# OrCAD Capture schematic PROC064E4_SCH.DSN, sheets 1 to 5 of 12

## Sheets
1 01. TABLE OF CONTENTS: title: TABLE OF CONTENTS; rev: E4; note: MS_TI_MAXIE_IDK_APPLICATION_CARD_SCH_REV E4
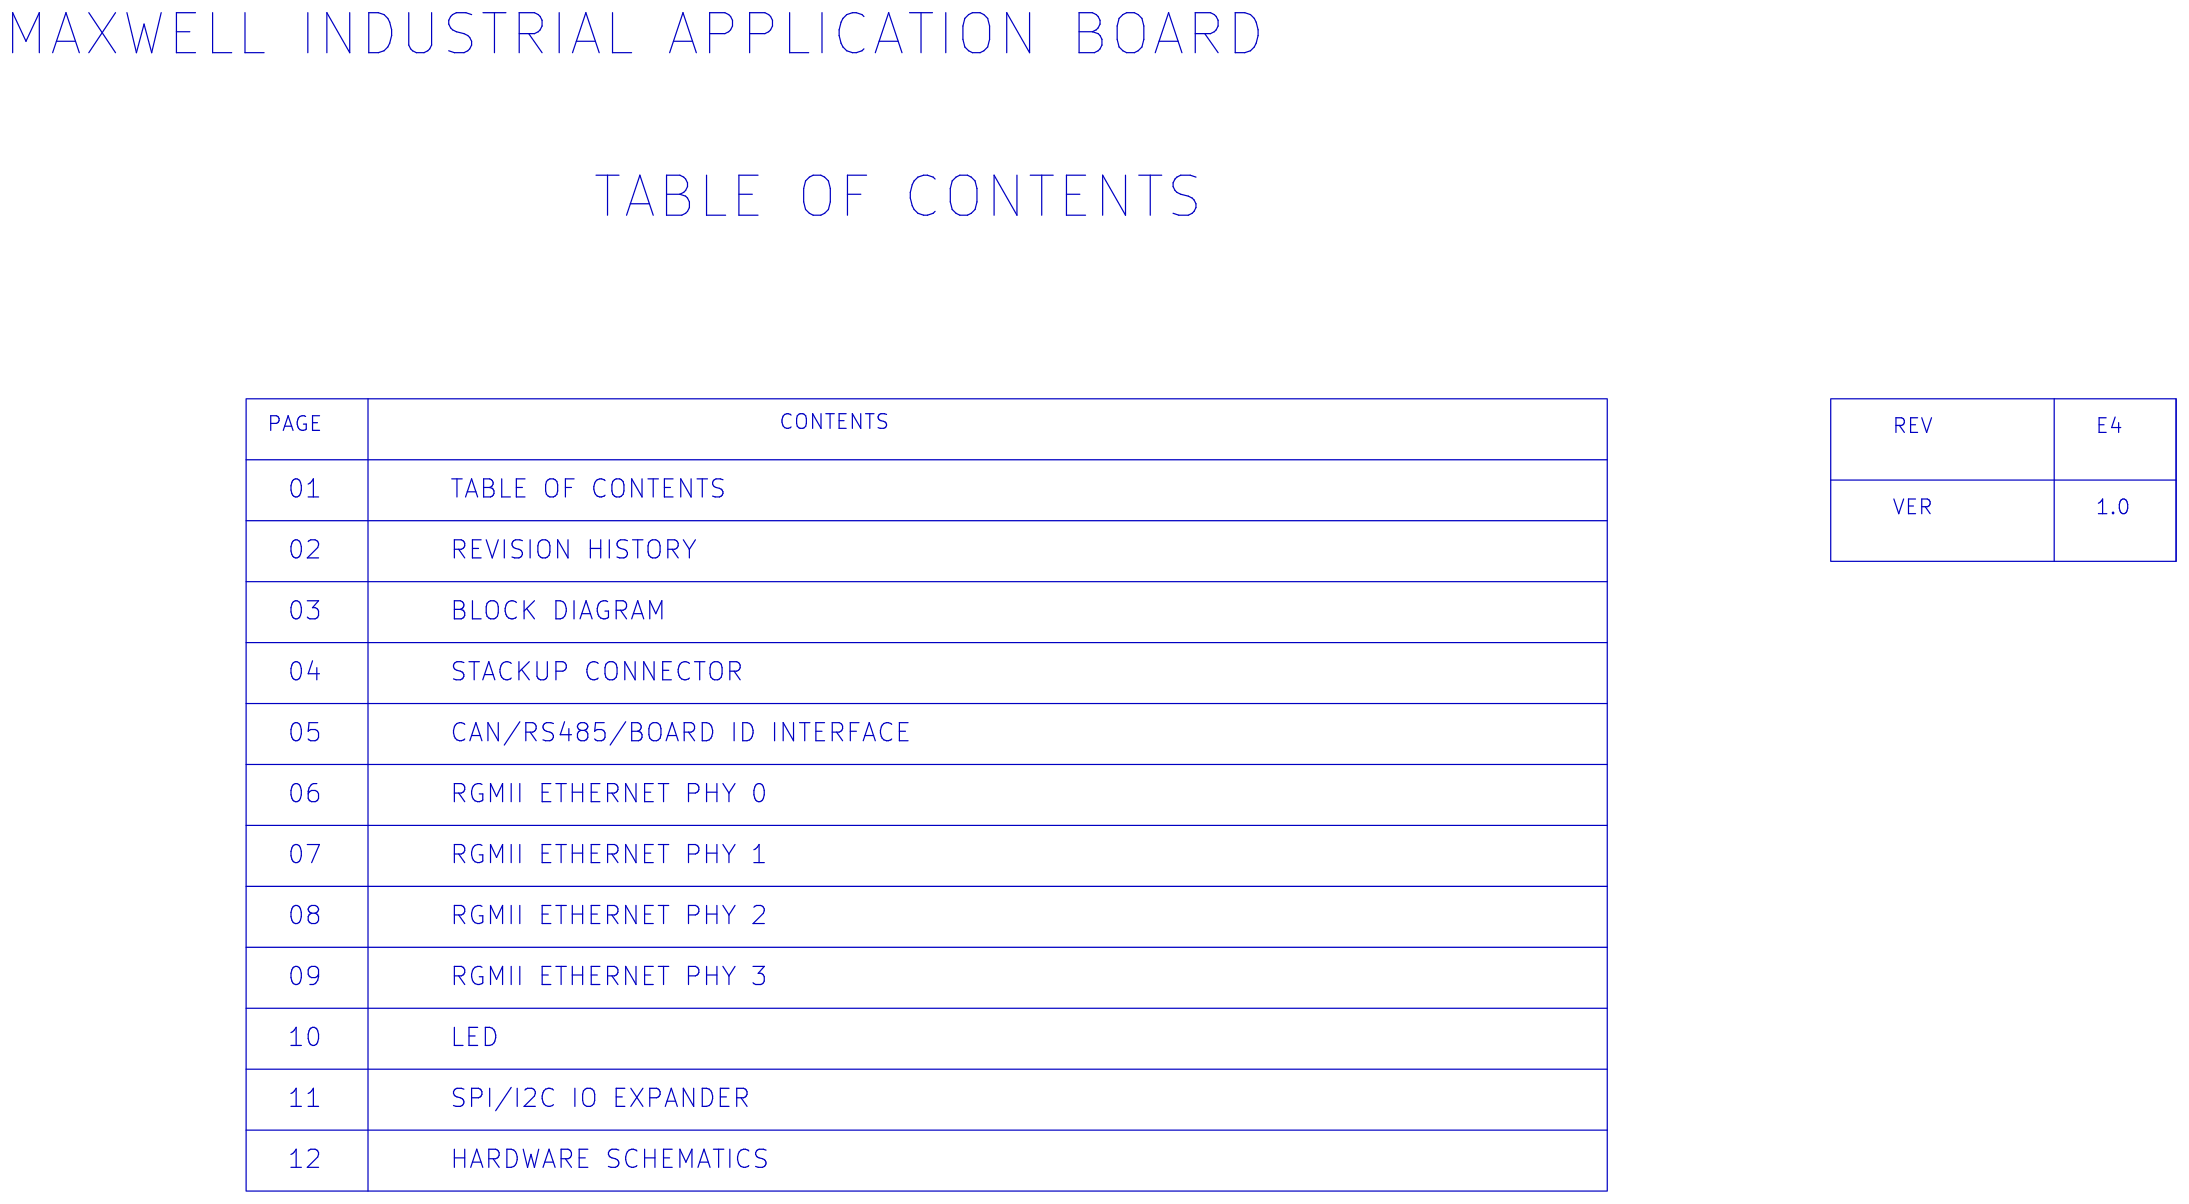
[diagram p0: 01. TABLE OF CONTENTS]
2 02. REVISION HISTORY: title: REVISION HISTORY
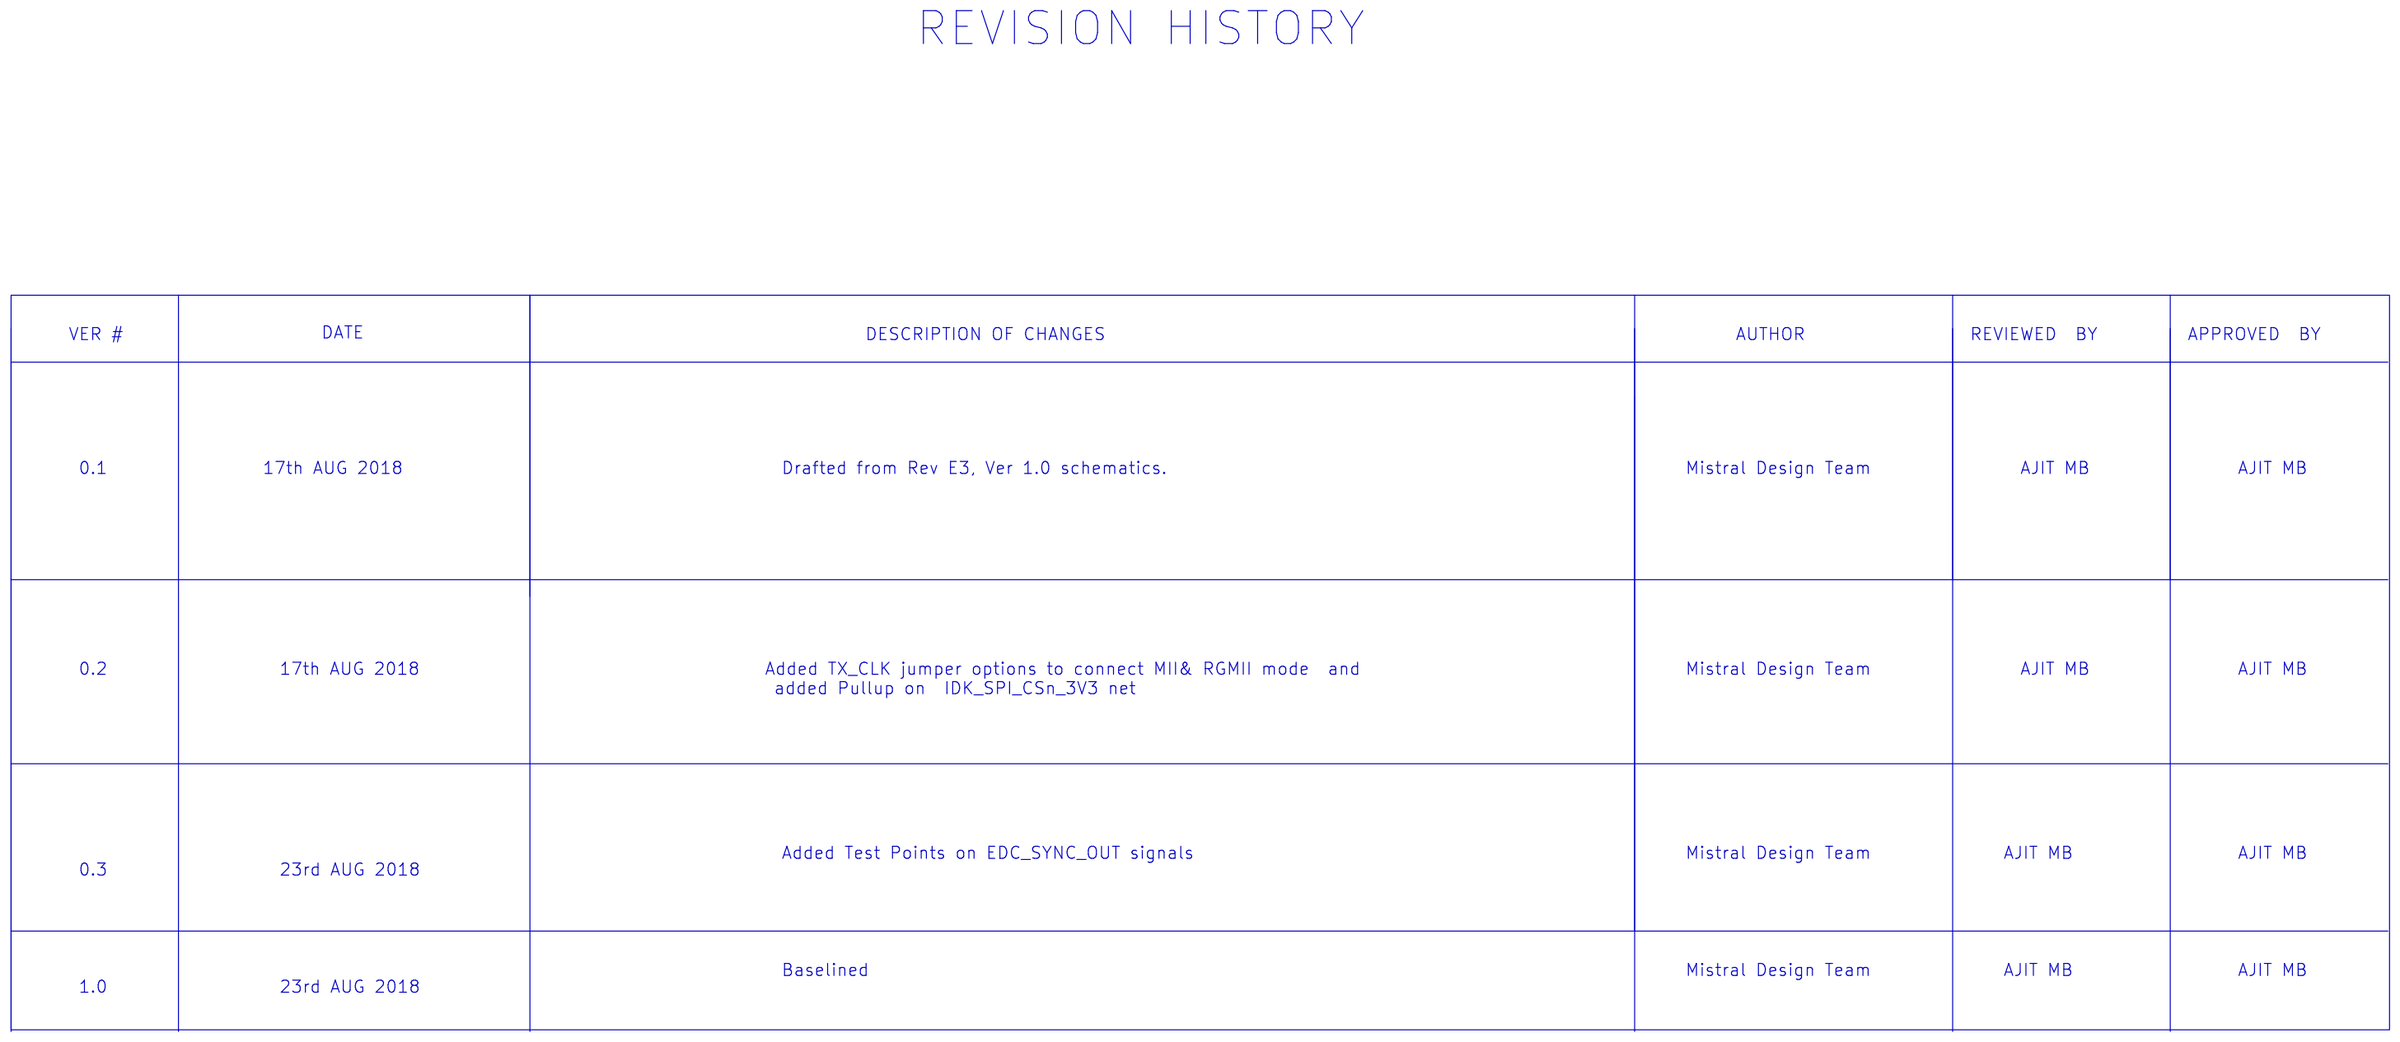
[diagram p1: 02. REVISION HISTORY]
3 03. BLOCK DIAGRAM: title: BLOCK DIAGRAM
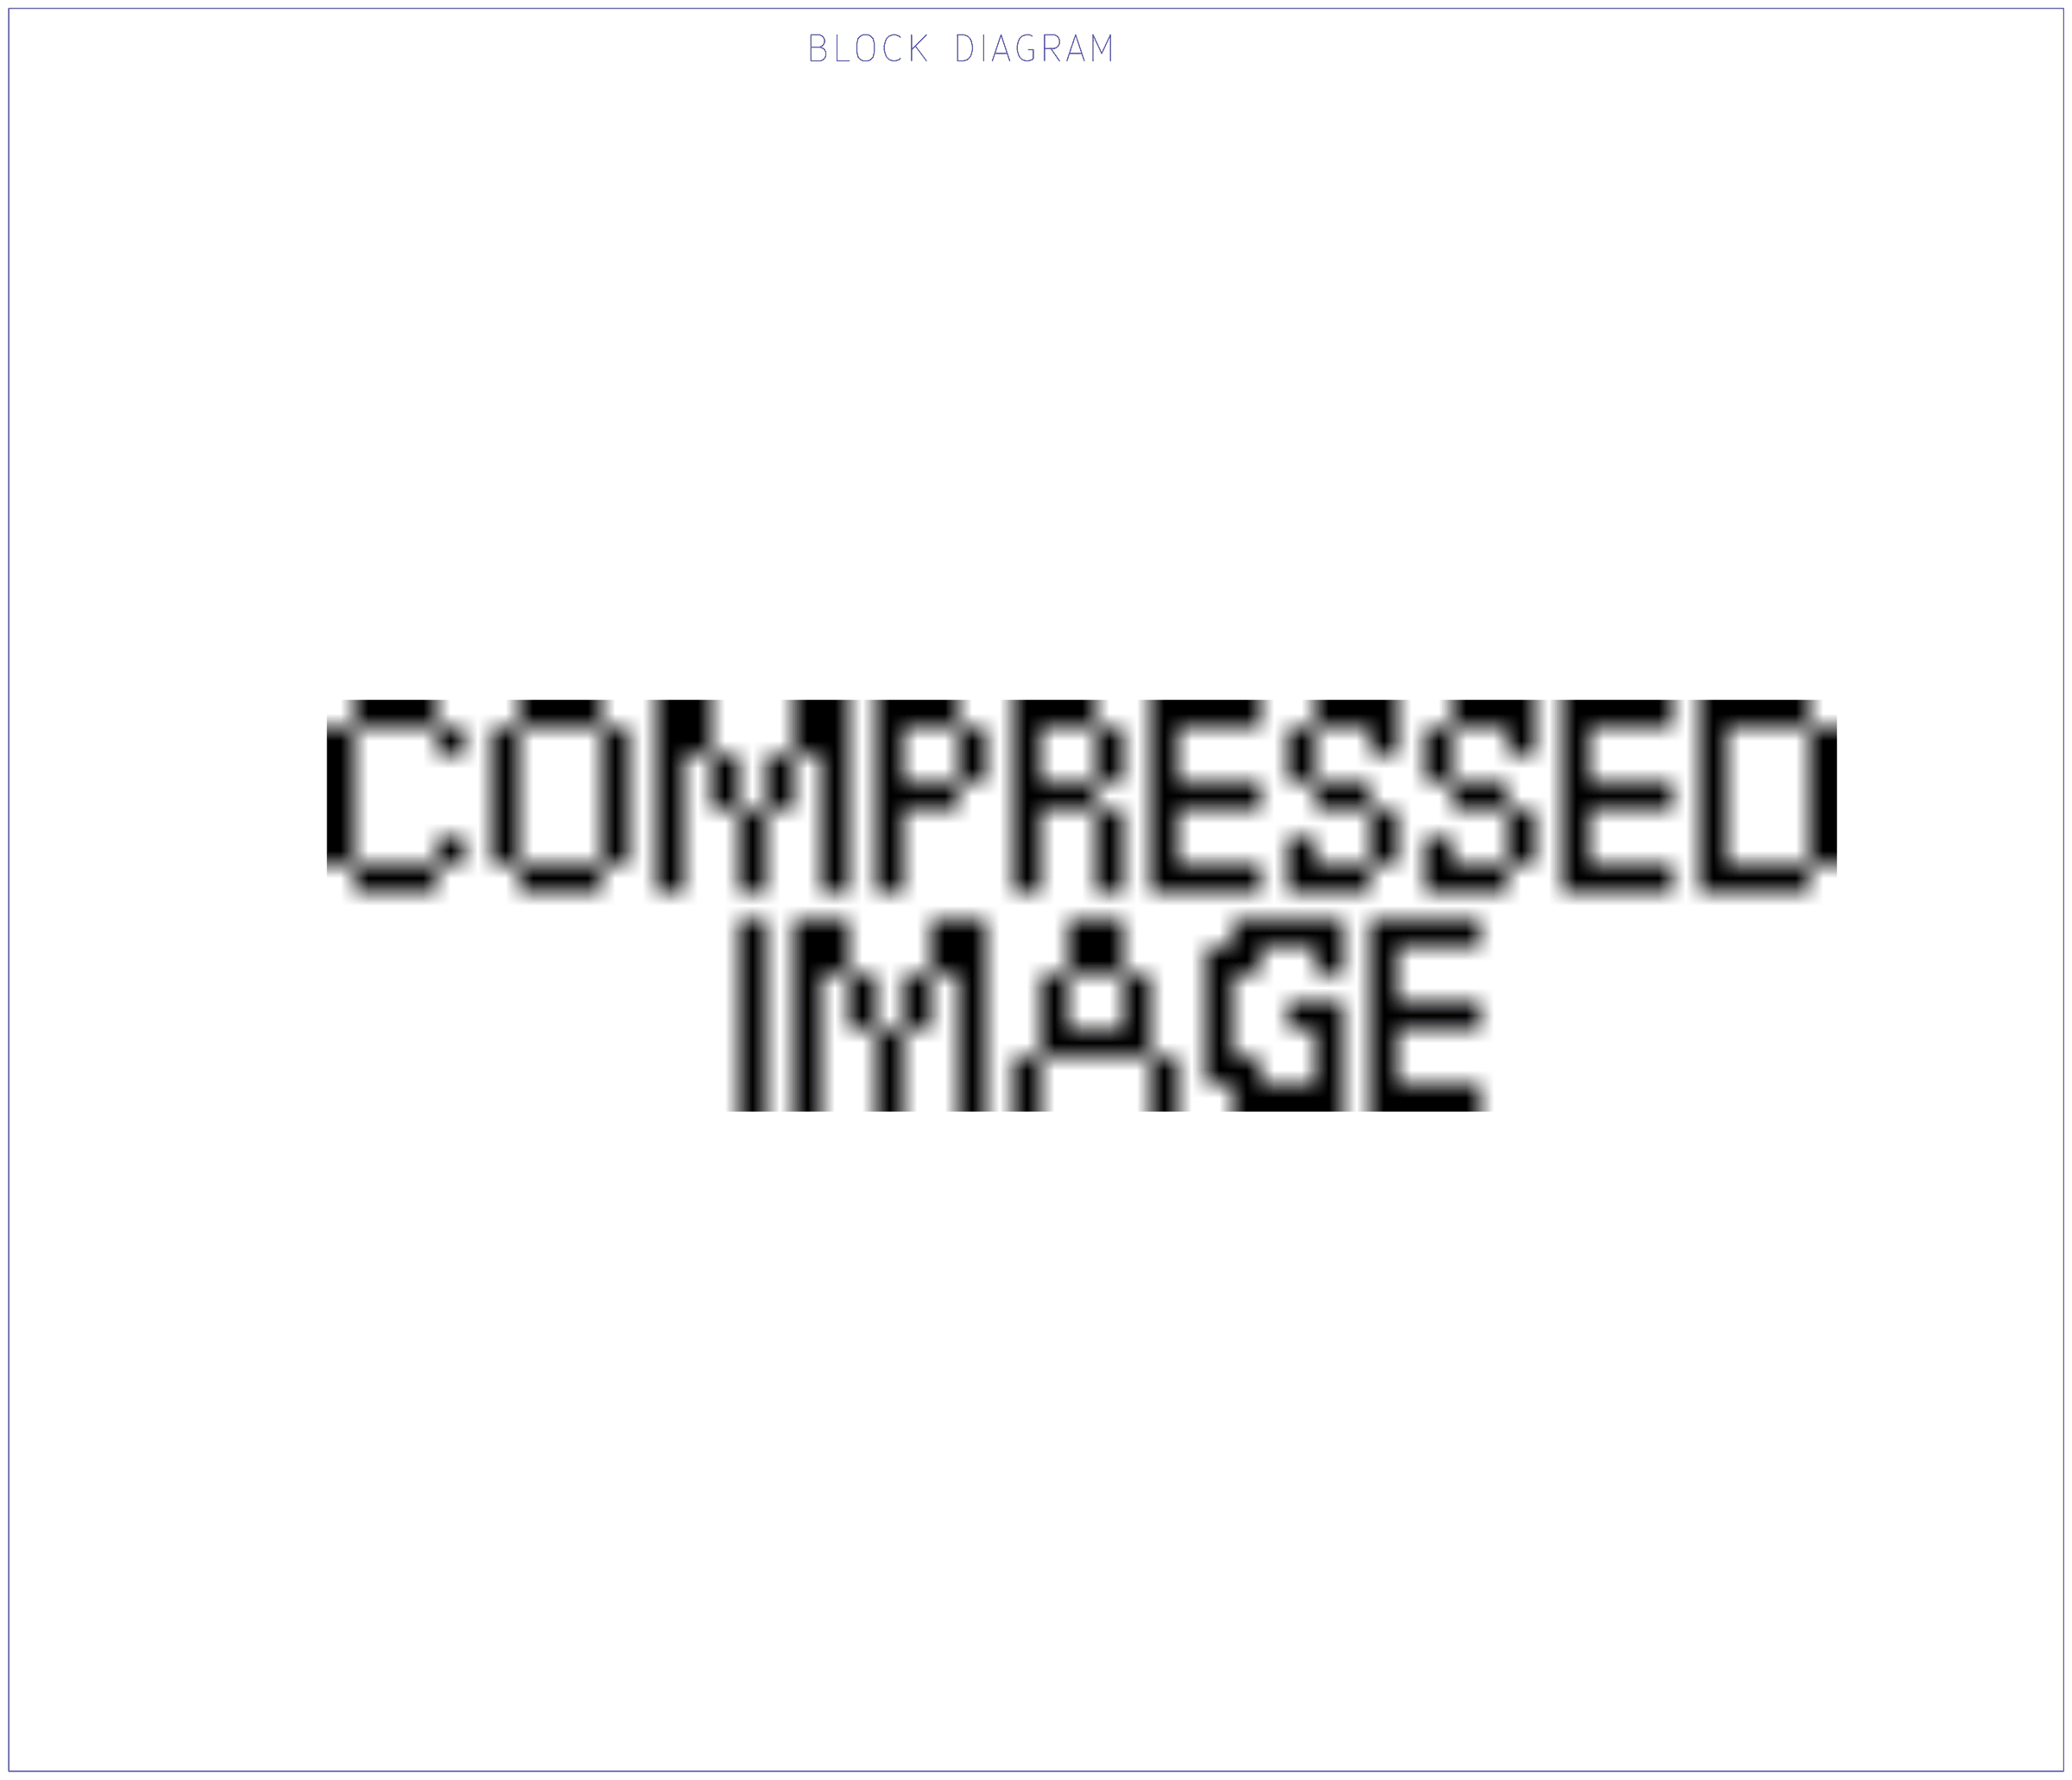
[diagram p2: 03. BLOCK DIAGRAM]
4 04. STACKUP CONNECTOR: size C; title: STACKUP CONNECTOR
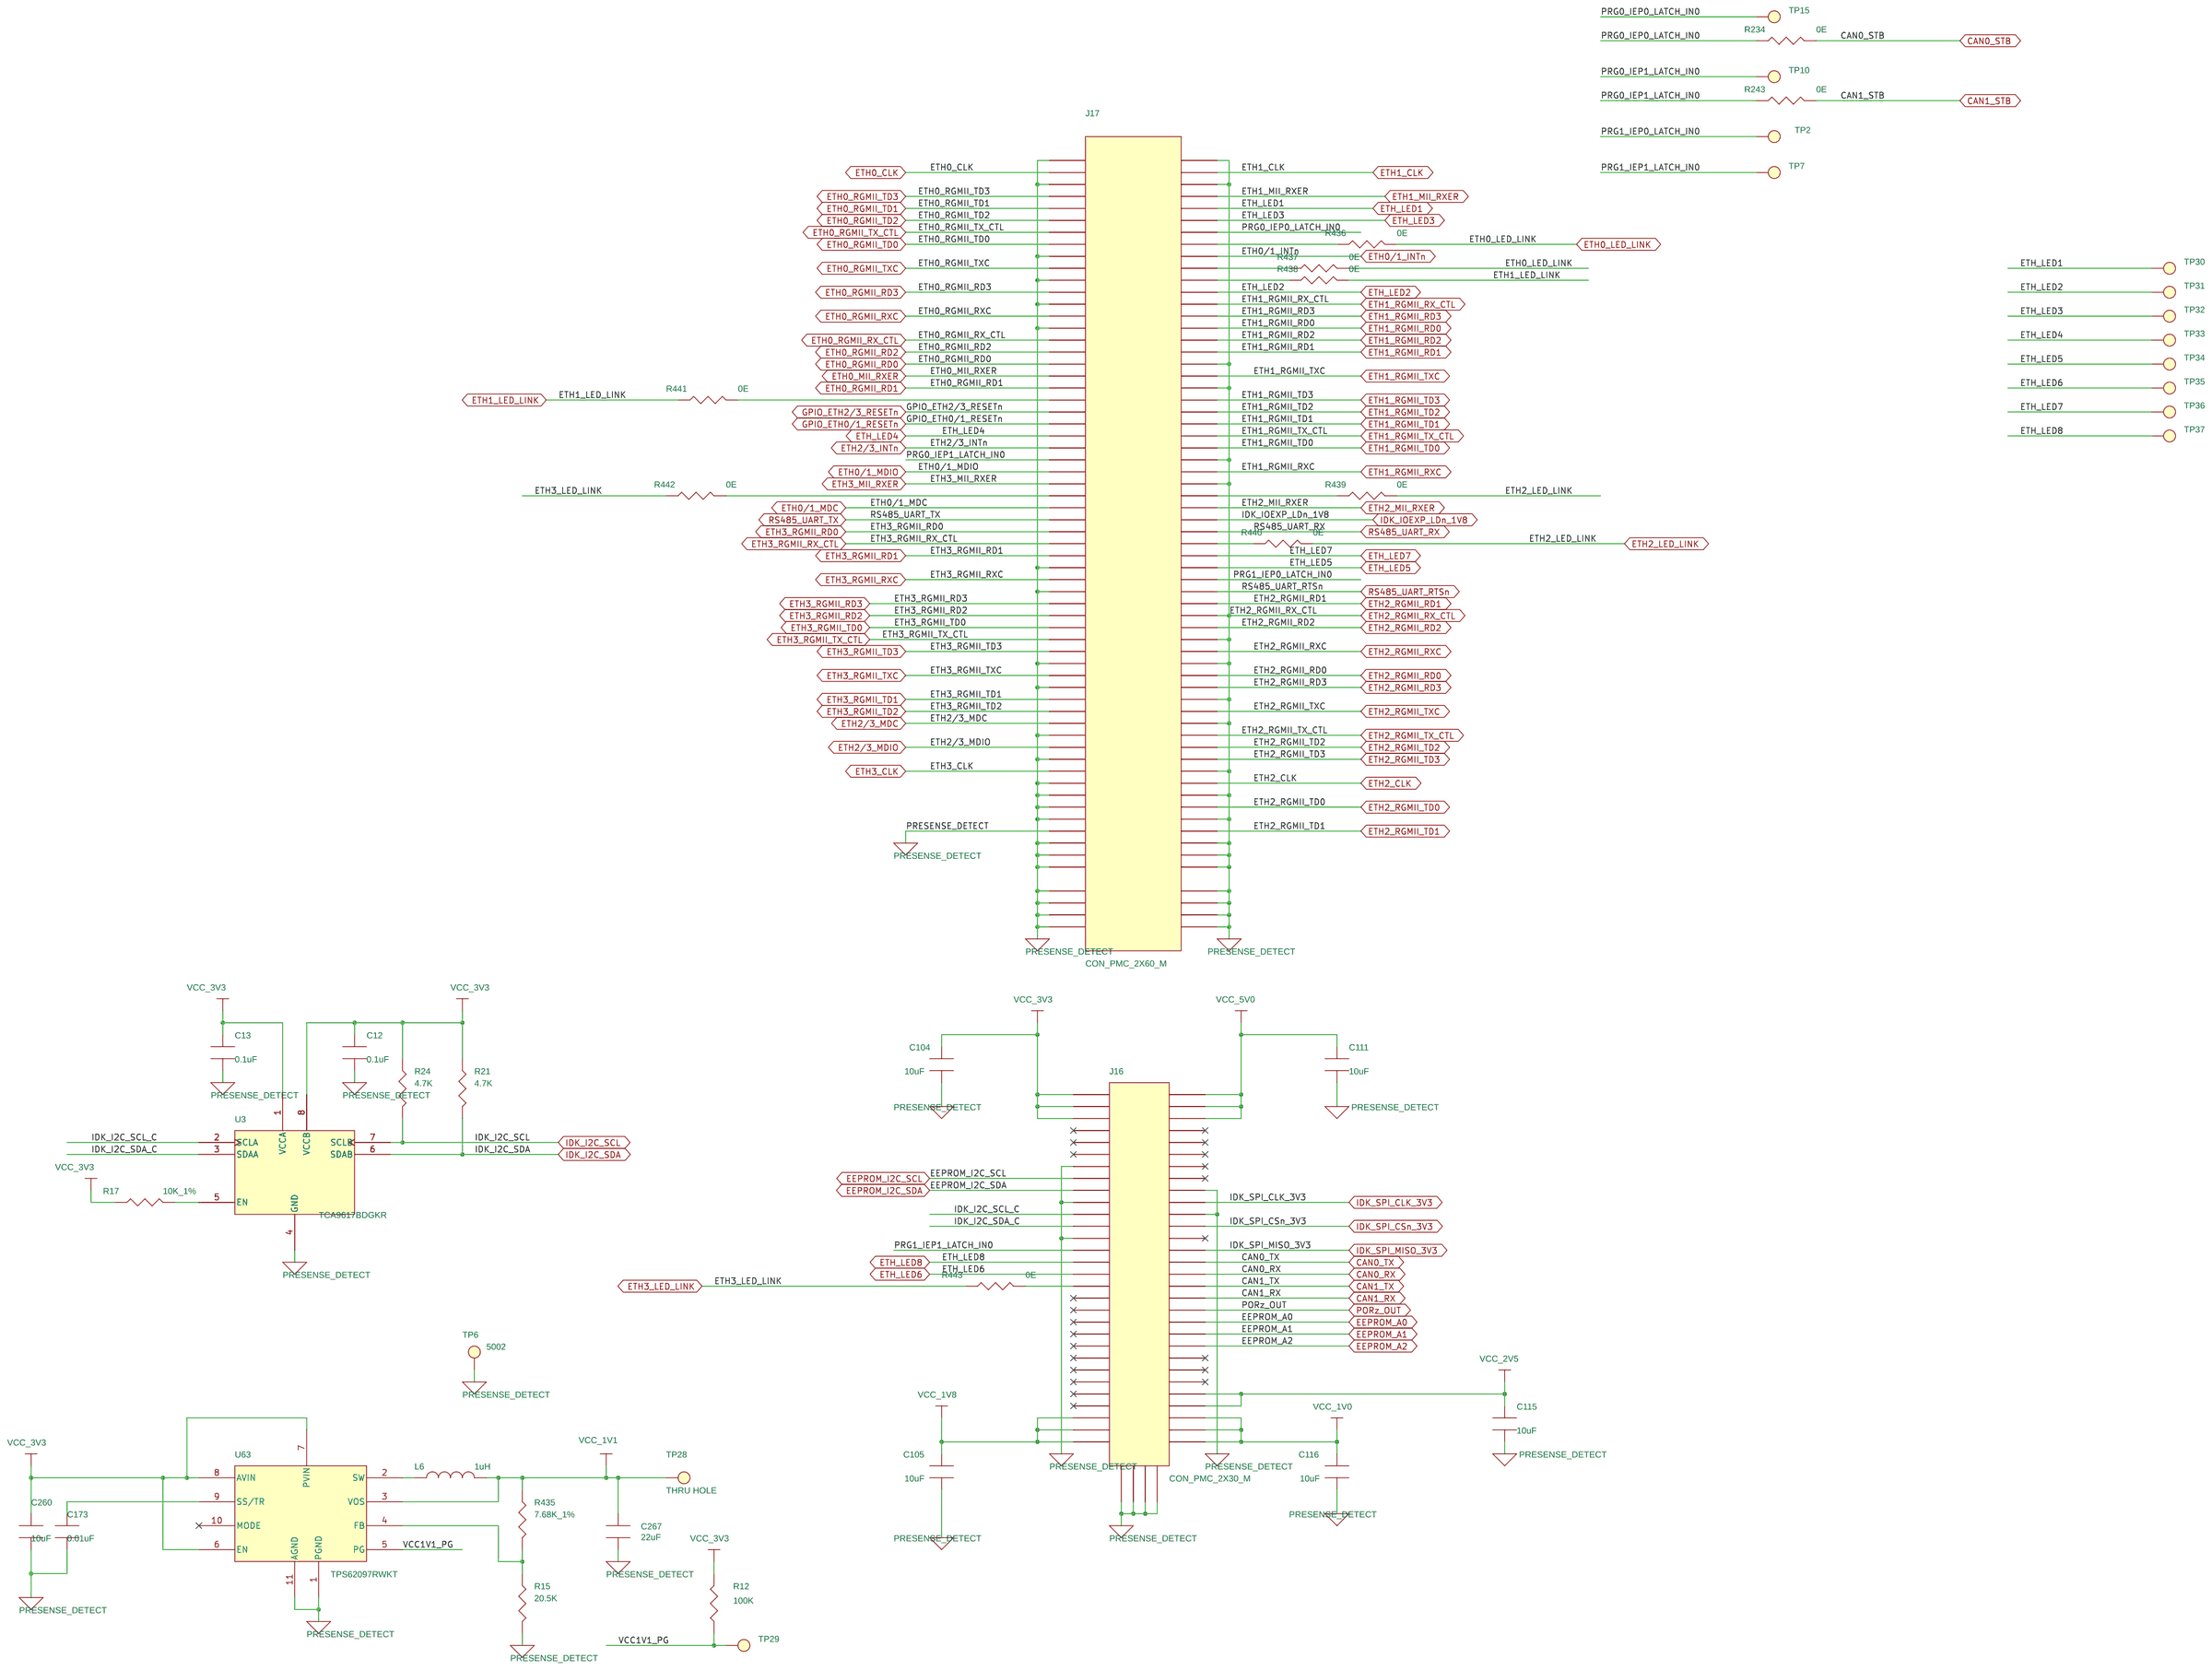
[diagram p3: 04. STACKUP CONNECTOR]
5 06. RGMII ETHERNET PHY 0: size C; title: RGMII ETHERNET PHY 0
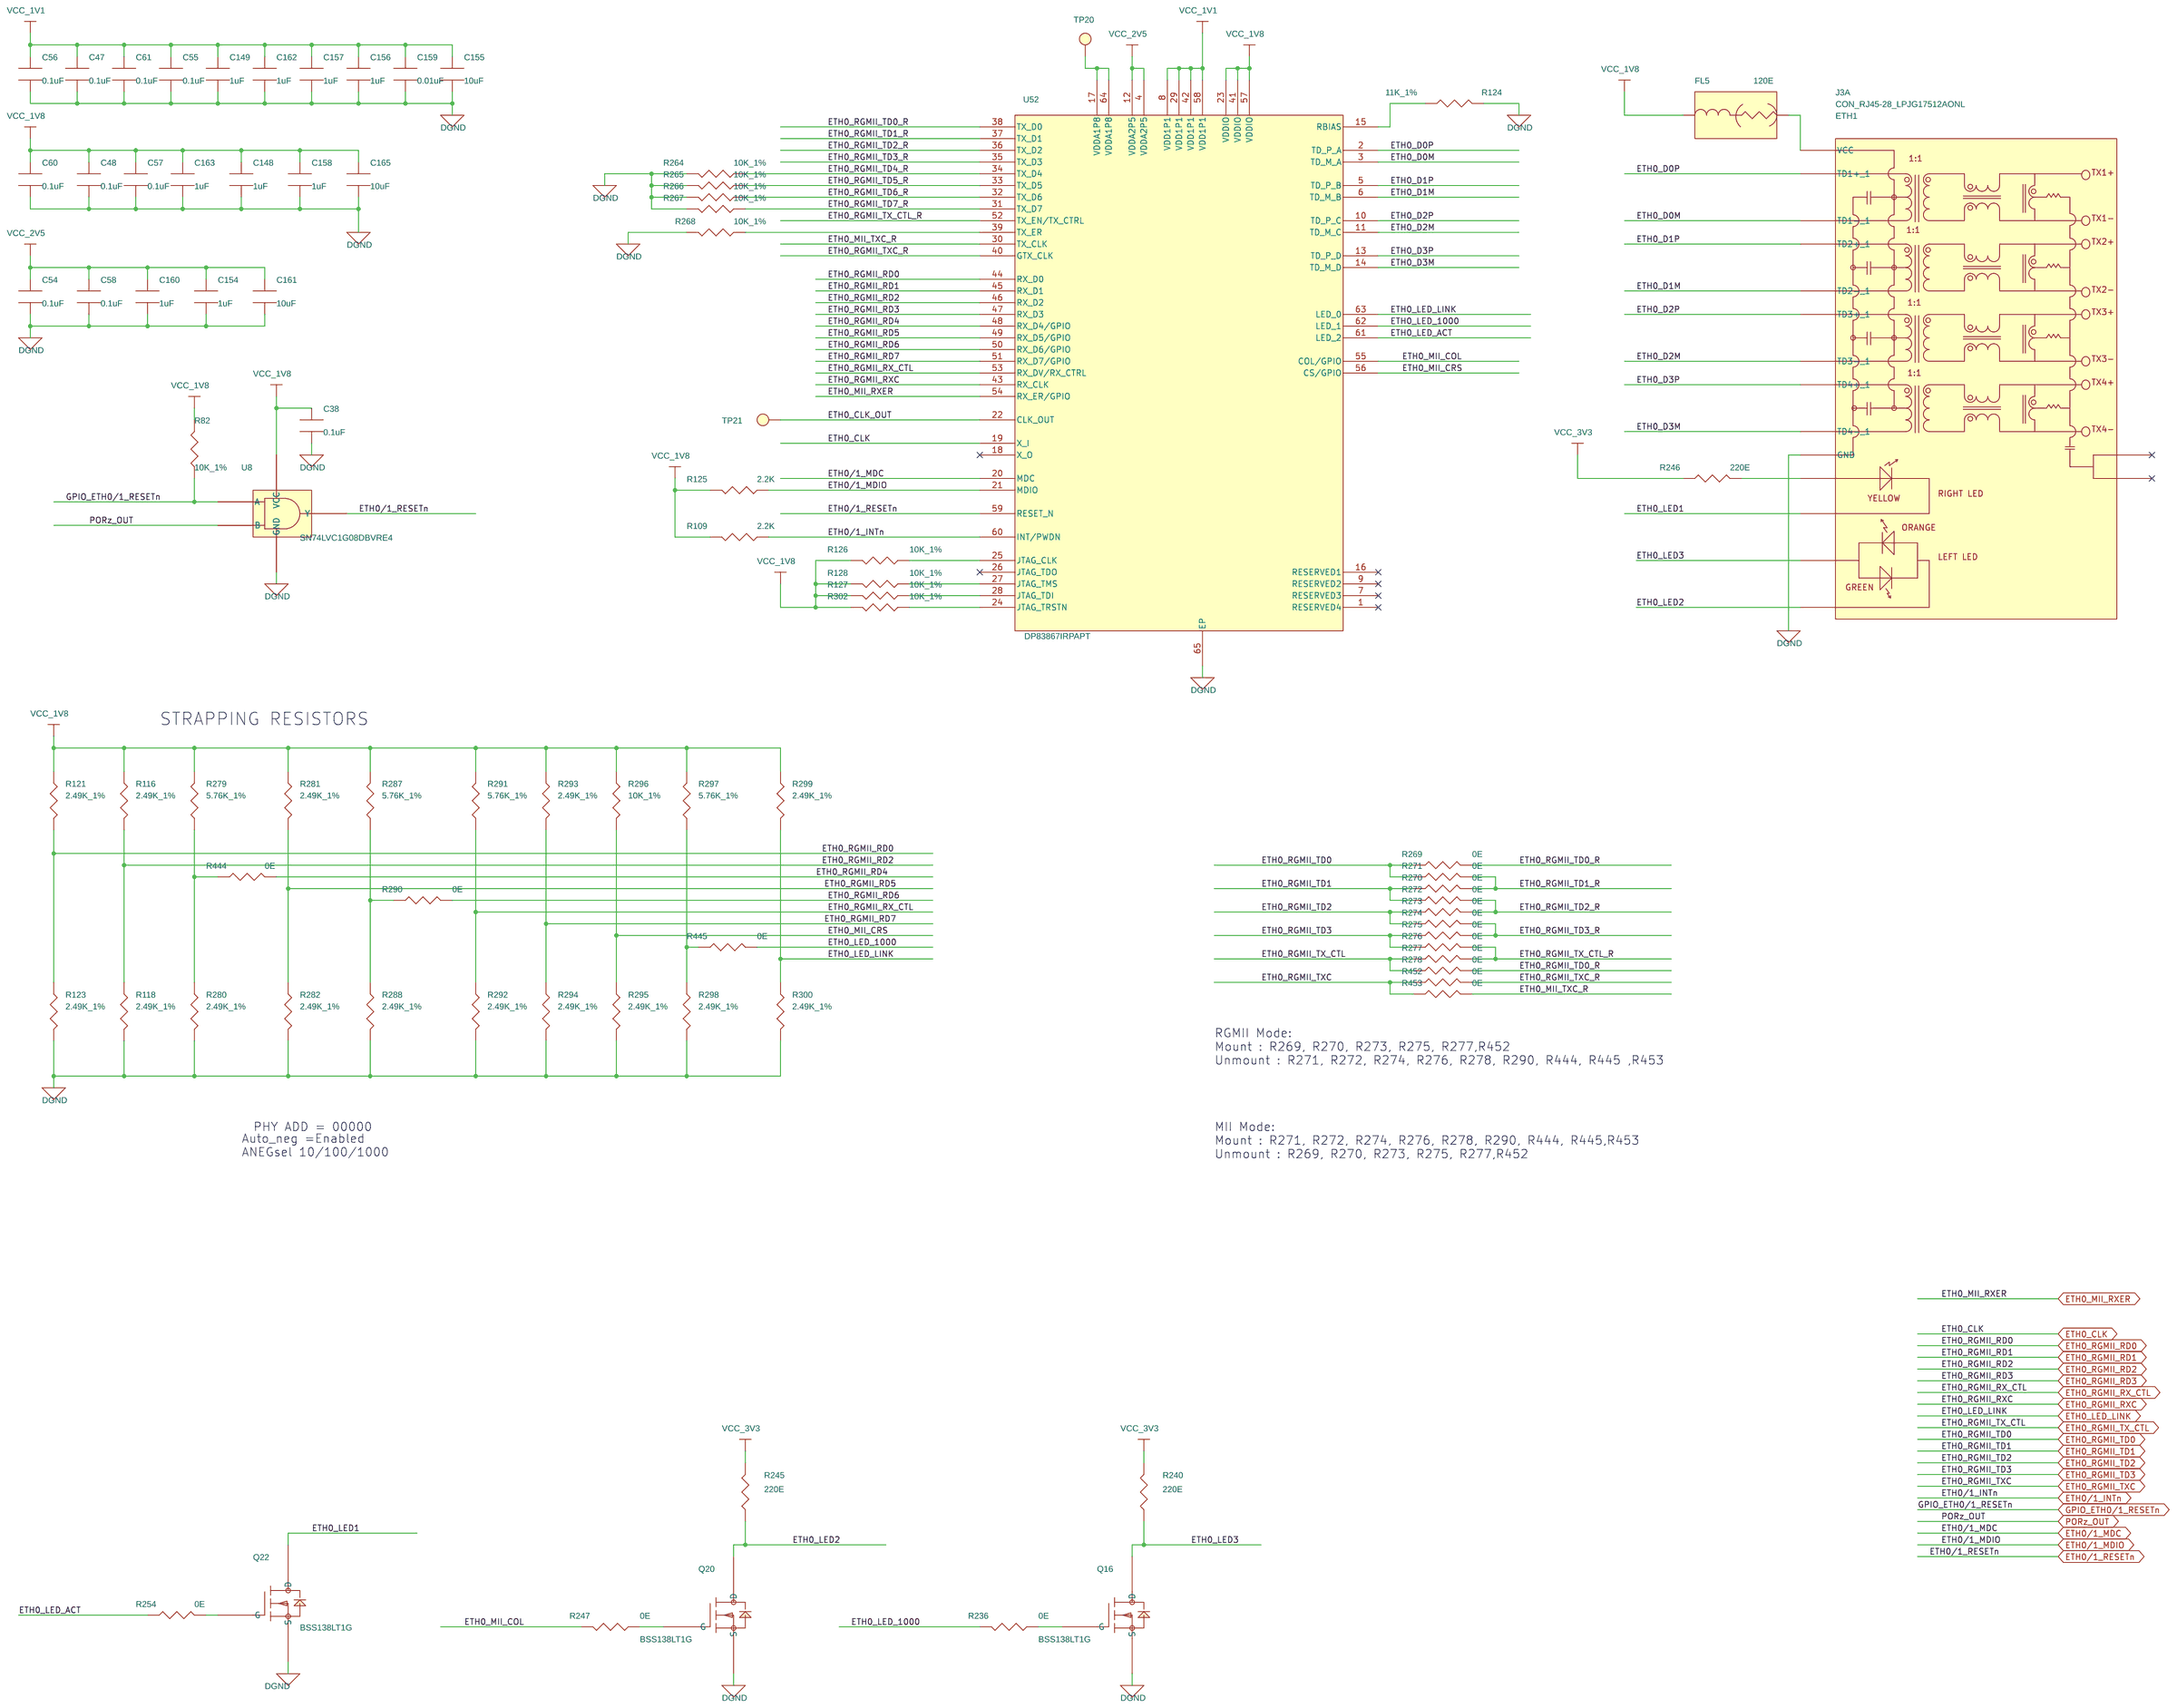
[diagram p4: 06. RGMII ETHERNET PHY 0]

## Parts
sheet 04. STACKUP CONNECTOR
C12  0.1uF  [CAP0402_0-75]
C13  0.1uF  [CAP0402_0-75]
C104  10uF  [CAP0603_1]
C105  10uF  [CAP0603_1]
C111  10uF  [CAP0603_1]
C115  10uF  [CAP0603_1]
C116  10uF  [CAP0603_1]
C173  0.01uF  [CAP0201_0-5]
C260  10uF  [CAP0603_1]
C267  22uF  [CAP0603_1]
J16  CON_PMC_2X30_M  [CON_PMC2X30_QTH-30_P_S_S_4-3]
J17  CON_PMC_2X60_M  [CON_PMC2X60_QTH-60-1-D-A_P_S_S_4-4]
L6  1uH  [IND_IHLP2020AB_210X210_SMD_1-2]
R12  100K  [RES0402_0-5]
R15  20.5K  [RES0402]
R17  10K_1%  [RES0402_0-5]
R21  4.7K  [RES0402]
R24  4.7K  [RES0402]
R234  0E  [RES0402_0-5]
R243  0E  [RES0402_0-5]
R435  7.68K_1%  [RES0402]
R436  0E  [RES0402_0-5]
R437  0E  [RES0402_0-5]
R438  0E  [RES0402_0-5]
R439  0E  [RES0402_0-5]
R440  0E  [RES0402_0-5]
R441  0E  [RES0402_0-5]
R442  0E  [RES0402_0-5]
R443  0E  [RES0402_0-5]
TP2  TP40_SMD  [TP40_SMD]
TP6  5002  [TP_CIR67D40_TH_4-6]
TP7  TP40_SMD  [TP40_SMD]
TP10  TP40_SMD  [TP40_SMD]
TP15  TP40_SMD  [TP40_SMD]
TP28  THRU HOLE  [TP_40X65]
TP29  TP40_SMD  [TP40_SMD]
TP30  TP40_SMD  [TP40_SMD]
TP31  TP40_SMD  [TP40_SMD]
TP32  TP40_SMD  [TP40_SMD]
TP33  TP40_SMD  [TP40_SMD]
TP34  TP40_SMD  [TP40_SMD]
TP35  TP40_SMD  [TP40_SMD]
TP36  TP40_SMD  [TP40_SMD]
TP37  TP40_SMD  [TP40_SMD]
U3  TCA9617BDGKR  [VSSOP8_25-59_120X120_1-1]
U63  TPS62097RWKT  [VQFNHR11_TPS62097_80X80_1]
sheet 06. RGMII ETHERNET PHY 0
C38  0.1uF  [CAP0402_0-75]
C47  0.1uF  [CAP0402_0-75]
C48  0.1uF  [CAP0402_0-75]
C54  0.1uF  [CAP0402_0-75]
C55  0.1uF  [CAP0402_0-75]
C56  0.1uF  [CAP0402_0-75]
C57  0.1uF  [CAP0402_0-75]
C58  0.1uF  [CAP0402_0-75]
C60  0.1uF  [CAP0402_0-75]
C61  0.1uF  [CAP0402_0-75]
C148  1uF  [CAP0402_0-75]
C149  1uF  [CAP0402_0-75]
C154  1uF  [CAP0402_0-75]
C155  10uF  [CAP0603_1]
C156  1uF  [CAP0402_0-75]
C157  1uF  [CAP0402_0-75]
C158  1uF  [CAP0402_0-75]
C159  0.01uF  [CAP0402]
C160  1uF  [CAP0402_0-75]
C161  10uF  [CAP0603_1]
C162  1uF  [CAP0402_0-75]
C163  1uF  [CAP0402_0-75]
C165  10uF  [CAP0603_1]
FL5  120E  [EMIFIL_BLM15A_0402_0-6]
J3  CON_RJ45-28_LPJG17512AONL  [CON_RJ45-28_LPJG17512_S_R_T_25-3]  (sections A,B)
Q16  BSS138LT1G  [SOT23-123]
Q20  BSS138LT1G  [SOT23-123]
Q22  BSS138LT1G  [SOT23-123]
R82  10K_1%  [RES0402_0-5]
R109  2.2K  [RES0402_0-5]
R116  2.49K_1%  [RES0402]
R118  2.49K_1%  [RES0402]
R121  2.49K_1%  [RES0402]
R123  2.49K_1%  [RES0402]
R124  11K_1%  [RES0402_0-5]
R125  2.2K  [RES0402_0-5]
R126  10K_1%  [RES0402_0-5]
R127  10K_1%  [RES0402_0-5]
R128  10K_1%  [RES0402_0-5]
R236  0E  [RES0402_0-5]
R240  220E  [RES0402_0-5]
R245  220E  [RES0402_0-5]
R246  220E  [RES0402_0-5]
R247  0E  [RES0402_0-5]
R254  0E  [RES0402_0-5]
R264  10K_1%  [RES0402_0-5]
R265  10K_1%  [RES0402_0-5]
R266  10K_1%  [RES0402_0-5]
R267  10K_1%  [RES0402_0-5]
R268  10K_1%  [RES0402_0-5]
R269  0E  [RES0402_0-5]
R270  0E  [RES0402_0-5]
R271  0E  [RES0402_0-5]
R272  0E  [RES0402_0-5]
R273  0E  [RES0402_0-5]
R274  0E  [RES0402_0-5]
R275  0E  [RES0402_0-5]
R276  0E  [RES0402_0-5]
R277  0E  [RES0402_0-5]
R278  0E  [RES0402_0-5]
R279  5.76K_1%  [RES0402]
R280  2.49K_1%  [RES0402]
R281  2.49K_1%  [RES0402]
R282  2.49K_1%  [RES0402]
R287  5.76K_1%  [RES0402]
R288  2.49K_1%  [RES0402]
R290  0E  [RES0402_0-5]
R291  5.76K_1%  [RES0402]
R292  2.49K_1%  [RES0402]
R293  2.49K_1%  [RES0402]
R294  2.49K_1%  [RES0402]
R295  2.49K_1%  [RES0402]
R296  10K_1%  [RES0402_0-5]
R297  5.76K_1%  [RES0402]
R298  2.49K_1%  [RES0402]
R299  2.49K_1%  [RES0402]
R300  2.49K_1%  [RES0402]
R302  10K_1%  [RES0402_0-5]
R444  0E  [RES0402_0-5]
R445  0E  [RES0402_0-5]
R452  0E  [RES0402_0-5]
R453  0E  [RES0402_0-5]
TP20  TP40_SMD  [TP40_SMD]
TP21  TP40_SMD  [TP40_SMD]
U8  SN74LVC1G08DBVRE4  [SOT23-5]
U52  DP83867IRPAPT  [EQFP64_19-68_400X400]

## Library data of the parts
C12 C13 C38 C47 C48 C54-C58 C60 C61 = CAP: CAP CERAMIC 0.1uF 25V 10% X5R 0402; Chkd/date: MANIRAJA/210817; Crtd /date: MANIRAJA/210817; Custom_Duty: 15%; Customs_HS_Code: 85322990; Distributor_name: DIGIKEY; Distributor_part_number: 490-5920-1-ND; Footprint Path: Y:\MIS_DATABASE\Library\ALTIUM_TOOL\PCB_FOOTPRINTS\Altium_Footprint_Lib.PcbLib; Height: 0.55MM; Library Path: Y:\MIS_DATABASE\Library\ALTIUM_TOOL\SCHEMATICS_PARTS\MS_DISCRETE_Library.schlib; Mfr_name: MURATA; Mfr_part_number: GRM155R61E104KA87D; Mistral Part No: 120017080016-R; Package: 0402; Part_type: CAPACITORS\CERAMIC; Project: TI_RF_DC CARD; RoHS: RoHS; Temperature: -55°C+85°C; Tolerance: 10%; Voltage: 25V; Wattage: NA; Weight: 11mg; Datasheet: Y:\MIS_DATABASE\DATASHEETS\CAPACITORS\GRM188SERIES.PDF
C104 C105 C111 C115 C116 C155 C161 C165 = CAP: CAP CERAMIC 10uF 25V 20% X5R 0603; Chkd/date: MANIRAJA/130617; Crtd /date: MUDDU/130810; Custom_Duty: 15%; Customs_HS_Code: 85322990; Distributor_name: DIGIKEY; Distributor_part_number: 490-7202-1-ND; Height: 0.90MM; Mfr_name: MURATA; Mfr_part_number: GRM188R61E106MA73D; Mistral Part No: 120010080005-R; Package: 0603; Part_type: CAPACITORS\CERAMIC; Project: PB_BUGBASE; RoHS: RoHS; Temperature: -55°C+85°C; Tolerance: 20%; Voltage: 25V; Wattage: NA; Weight: 6.3mg; Datasheet: Y:\MIS_DATABASE\DATASHEETS\CAPACITORS\MURATA_CMCC.PDF
C173 = CAP: CAP CERAMIC 0.01uF 25V 10% X5R 0201; Chkd/date: MANIRAJA/230118; Crtd /date: MANIRAJA/230118; Custom_Duty: 15%; Customs_HS_Code: 85322990; Distributor_name: DIGIKEY; Distributor_part_number: GRM033R61E103KA12J-ND; Height: 0.33MM; Mfr_name: MURATA; Mfr_part_number: GRM033R61E103KA12J; Mistral Part No: 120018010007-R; Package: 0201; Part_type: CAPACITORS\CERAMIC; Project: TI_MAXIE_CPB; RoHS: RoHS; Temperature: -55°C+85°C; Tolerance: 10%; Voltage: 25V; Wattage: NA; Weight: 0.33mg; Datasheet: Y:\MIS_DATABASE\DATASHEETS\CAPACITORS\GRM033R61E103KA12.PDF
C260 = CAP: CAP CERAMIC 10uF 10V 10% X5R 0603; Chkd/date: MANIRAJA/230118; Crtd /date: MANIRAJA/230118; Custom_Duty: 15%; Customs_HS_Code: 85322990; Distributor_name: DIGIKEY; Distributor_part_number: 478-10766-1-ND; Height: 0.94MM; Mfr_name: AVX CORPORATION; Mfr_part_number: 0603ZD106KAT2A; Mistral Part No: 120010080001-R; Package: 0603; Part_type: CAPACITORS\CERAMIC; Project: TI_MAXIE_CPB; RoHS: RoHS; Temperature: -55°C+85°C; Tolerance: 10%; Voltage: 10V; Wattage: NA; Weight: 2mg; Datasheet: Y:\MIS_DATABASE\DATASHEETS\CAPACITORS\AVX_MLC.PDF
C267 = CAP: CAP CERAMIC 22uF 6.3V 20% X5R 0603; Chkd/date: MANIRAJA/230118; Crtd /date: MANIRAJA/230118; Custom_Duty: 15%; Customs_HS_Code: 85322990; Distributor_name: DIGIKEY; Distributor_part_number: 490-10476-1-ND; Height: 1.00MM; Mfr_name: MURATA; Mfr_part_number: GRM188R60J226MEA0D; Mistral Part No: 120014100009-R; Package: 0603; Part_type: CAPACITORS\CERAMIC; Project: TI_MAXIE_CPB; RoHS: RoHS; Temperature: -55°C+85°C; Tolerance: 20%; Voltage: 6.3V; Wattage: NA; Weight: 6.3mg; Datasheet: Y:\MIS_DATABASE\DATASHEETS\CAPACITORS\GRM188R61A226ME15.PDF
J16 = CON_PMC_30X2_M: CON PMC 2X30 0.50MM PITCH MALE ST SMD; Chkd/date: MANIRAJA/180717; Crtd /date: USMAN/311008; Custom_Duty: 24%; Customs_HS_Code: 85369090; Distributor_name: DIGIKEY; Distributor_part_number: SAM8185-ND; Height: 4.27MM; Mfr_name: SAMTEC; Mfr_part_number: QTH-030-01-L-D-A; Mistral Part No: 150009030609-R; Package: SMD; Part_type: CONNECTOR\PMC; Project: KHAN_HSST; RoHS: RoHS; TEXT: CP; Temperature: -55°C+125°C; Tolerance: NA; Voltage: NA; Wattage: NA; Weight: NA; Datasheet: Y:\MIS_DATABASE\DATASHEETS\CONNECTORS\QTH.PDF
J17 = CON_INT_60X2_M: CON PMC 2X60 0.50MM PITCH MALE ST SMD; Chkd/date: MANIRAJA/301117; Crtd /date: ALVY/301117; Custom_Duty: 24%; Customs_HS_Code: 85369090; Distributor_name: DIGIKEY; Distributor_part_number: SAM8189-ND; Height: 4.35MM; Mfr_name: SAMTEC; Mfr_part_number: QTH-060-01-L-D-A; Mistral Part No: 150017110027-R; Package: SMD; Part_type: CONNECTOR\PMC; Project: RSAPR_TYPE-II_CPLD; RoHS: RoHS; Temperature: -55°C+125°C; Tolerance: NA; Voltage: NA; Wattage: NA; Weight: NA; Datasheet: Y:\MIS_DATABASE\DATASHEETS\CONNECTORS\QTH-GP-SER.PDF
L6 = INDUCTOR: IND POWER 1uH 4.4A 20% SMD; Chkd/date: VASANTHA/170317; Crtd /date: MANIRAJA/160317; Custom_Duty: 24%; Customs_HS_Code: 85437099; Distributor_name: DIGIKEY; Distributor_part_number: 541-1704-1-ND; Height: 1.20MM; Mfr_name: VISHAY; Mfr_part_number: IHLP2020ABER1R0M01; Mistral Part No: 130017030015-R; Package: SMD; Project: ADA_3U_FMC; RoHS: RoHS; Temperature: -55°C+125°C; Tolerance: 20%; Voltage: NA; Wattage: NA; Weight: 200mg; Datasheet: Y:\MIS_DATABASE\DATASHEETS\DISCRETES\INDUCTORS\IHLP2020AB.PDF
R12 = RESISTOR: RES 100K 1/16W 5% 0402; Chkd/date: VASANTHA/061216; Crtd /date: BAVISH/010611; Custom_Duty: 15%; Customs_HS_Code: 85332119; Distributor_name: DIGIKEY; Distributor_part_number: 541-100KJCT-ND; Height: 0.40MM; Mfr_name: VISHAY; Mfr_part_number: CRCW0402100KJNED; Mistral Part No: 110011060002-R; Package: 0402; Part_type: RESISTORS\FIXED; Project: AM4515_EVM_LCD; RoHS: RoHS; Temperature: -55°C+155°C; Tolerance: 5%; Voltage: NA; Wattage: 1/16W; Weight: 0.65mg; Datasheet: Y:\MIS_DATABASE\DATASHEETS\RESISTORS\CRCW0603.PDF
R15 = RESISTOR: RES 20.5K 1/10W 1% 0402; Chkd/date: MAZHAR/0141010; Crtd /date: BAVISH/290910; Custom_Duty: 15%; Customs_HS_Code: 85332119; Distributor_name: DIGIKEY; Distributor_part_number: P20.5KLCT-ND; Footprint Path: Y:\MIS_DATABASE\Library\ALTIUM_TOOL\PCB_FOOTPRINTS\Altium_Footprint_Lib.PcbLib; Height: 0.40MM; Library Path: Y:\MIS_DATABASE\Library\ALTIUM_TOOL\SCHEMATICS_PARTS\MS_DISCRETE_Library.schlib; Mfr_name: PANASONIC-ECG; Mfr_part_number: ERJ-2RKF2052X; Mistral Part No: 110010090063-R; Package: 0402; Part_type: RESISTORS\FIXED; Project: ITS; RoHS: RoHS; Temperature: -55°C+125°C; Tolerance: 1%; Wattage: 1/10W; Weight: 0.8/1000g; Datasheet: Y:\MIS_DATABASE\DATASHEETS\RESISTORS\ERJ2R.PDF
R17 R82 R126-R128 R264-R268 R296 R302 = RESISTOR: RES 10K 1/16W 1% 0402; Chkd/date: VASANTHA/201216; Crtd /date: GEETHA/290506; Custom_Duty: 15%; Customs_HS_Code: 85332119; Distributor_name: DIGIKEY; Distributor_part_number: 311-10.0KLRTR-ND; Footprint Path: Y:\MIS_DATABASE\Library\ALTIUM_TOOL\PCB_FOOTPRINTS\Altium_Footprint_Lib.PcbLib; Height: 0.40MM; Library Path: Y:\MIS_DATABASE\Library\ALTIUM_TOOL\SCHEMATICS_PARTS\MS_DISCRETE_Library.schlib; Mfr_name: YAGEO AMERICA; Mfr_part_number: RC0402FR-0710KL; Mistral Part No: 110009030220-P; Package: 0402; Part_type: RESISTORS\FIXED; Project: VOCERA; RoHS: Pb-Free; Temperature: -55°C+155°C; Tolerance: 1%; Voltage: NA; Wattage: 1/16W; Weight: 0.65mg; Datasheet: Y:\MIS_DATABASE\DATASHEETS\RESISTORS\YAGEO-RC0402.PDF
R21 R24 = RESISTOR: RES 4.7K 1/16W 5% 0402; Chkd/date: VASANTHA/130516; Crtd /date: VASANTHA/130516; Custom_Duty: 15%; Customs_HS_Code: 85332119; Distributor_name: DIGIKEY; Distributor_part_number: 311-4.7KJRCT-ND; Height: 0.55MM; Mfr_name: YAGEO AMERICA; Mfr_part_number: RC0402JR-074K7L; Mistral Part No: 110009030792-R; Package: 0402; Part_type: RESISTORS\FIXED; Project: TMDXCSK368; RoHS: RoHS; Temperature: -55°C+155°C; Tolerance: 5%; Voltage: NA; Wattage: 1/16W; Weight: NA; Datasheet: Y:\MIS_DATABASE\DATASHEETS\RESISTORS\YAGEO-RC0402.PDF
R234 R236 R243 R247 R254 R269-R278 R290 R436-R445 R452 R453 = RESISTOR: RES 0E 1/16W 0402; Chkd/date: VASANTHA/201216; Crtd /date: MUDDU/190810; Custom_Duty: 15%; Customs_HS_Code: 85332119; Distributor_name: DIGIKEY; Distributor_part_number: 541-0.0JCT-ND; Footprint Path: Y:\MIS_DATABASE\Library\ALTIUM_TOOL\PCB_FOOTPRINTS\Altium_Footprint_Lib.PcbLib; Height: 0.40MM; Library Path: Y:\MIS_DATABASE\Library\ALTIUM_TOOL\SCHEMATICS_PARTS\MS_DISCRETE_Library.schlib; Mfr_name: VISHAY; Mfr_part_number: CRCW04020000Z0ED; Mistral Part No: 110010080019-P; Package: 0402; Part_type: RESISTORS\FIXED; Project: PB_BUGBASE; RoHS: Pb-Free; Temperature: -55°C+155°C; Tolerance: NA; Voltage: NA; Wattage: 1/16W; Weight: 0.65g/1000pcs; Datasheet: Y:\MIS_DATABASE\DATASHEETS\RESISTORS\CRCW0603.PDF
R435 = RESISTOR: RES 7.68K 1/16W 1% 0402; Chkd/date: MAZHAR/0141010; Crtd /date: BAVISH/092410; Custom_Duty: 15%; Customs_HS_Code: 85332119; Distributor_name: DIGIKEY; Distributor_part_number: 541-7.68KLDKR-ND; Height: 0.40MM; Mfr_name: VISHAY; Mfr_part_number: CRCW04027K68FKED; Mistral Part No: 110010090051-R; Package: 0402; Part_type: RESISTORS\FIXED; Project: ITS; RoHS: RoHS; Temperature: -55°C+155°C; Tolerance: 1%; Wattage: 1/16W; Weight: 0.65mg; Datasheet: Y:\MIS_DATABASE\DATASHEETS\RESISTORS\CRCW0402-VISHAY.PDF
TP2 TP7 TP10 TP15 TP20 TP21 TP29-TP37 = TESTPOINT: TESTPOINT CIR 40 SMD; Chkd/date: MAZHAR/190505; Crtd /date: MAZHAR/190505; Distributor_name: NA; Distributor_part_number: NA; Footprint Path: Y:\MIS_DATABASE\Library\ALTIUM_TOOL\PCB_FOOTPRINTS\Altium_Footprint_Lib.PcbLib; Height: NA; Library Path: Y:\MIS_DATABASE\Library\ALTIUM_TOOL\SCHEMATICS_PARTS\MS_DISCRETE_Library.schlib; MECHANICAL 3D STEP FILE: NA; Mfr_name: LOCAL; Mistral Part No: 130009030933; Package: SMD; Project: RAINIER-3; RoHS: NA; Temperature: NA; Tolerance: NA; Voltage: NA; Wattage: NA; Weight: NA; Datasheet: NA
TP6 = TESTPOINT: ACCESSORIE PC TEST POINT; Chkd/date: VASANTHA/121216; Crtd /date: MANIRAJA/121216; Distributor_name: DIGIKEY; Distributor_part_number: 36-5002-ND; Height: 4.57MM; Mfr_name: KEYSTONE; Mistral Part No: 160016120008-R; Package: NA; Part_type: ACCESSORIES; Project: EPOS_EVM; RoHS: RoHS; Temperature: NA; Tolerance: NA; Voltage: NA; Wattage: NA; Weight: NA; Datasheet: Y:\MIS_DATABASE\DATASHEETS\MISC\ACCESSORIES\5002.PDF
TP28 = TESTPOINT: TESTPOINT 1.0MM DRILL PTH; Chkd/date: MAZHAR/271211; Crtd /date: SHREESHAIL/041005; Distributor_name: NA; Distributor_part_number: NA; Height: NA; Mfr_name: LOCAL; Mistral Part No: 130009030938; Package: THRU-HOLE; Part_type: MISC\TESTPOINT; Project: HSE; Datasheet: NA
U3 = TCA9617BDGKR_VSSOP8: IC FM+I2C BUS REPEATER LEVEL TRANSLATOR VSSOP8; Chkd/date: MANIRAJA/131017; Crtd /date: MANIRAJA/131017; Custom_Duty: 15%; Customs_HS_Code: 85423100; Distributor_name: DIGIKEY; Distributor_part_number: 296-40579-1-ND; Height: 1.10MM; Mfr_name: TEXAS INSTRUMENTS; Mistral Part No: 141017100010-R; Package: VSSOP8; Part_type: ICS\INTERFACE\LEVEL TRANSLATOR; Project: TI_MAXIE_CPB; RoHS: RoHS; Temperature: -40°C+85°C; Tolerance: NA; Voltage: NA; Wattage: NA; Weight: NA; Datasheet: Y:\MIS_DATABASE\DATASHEETS\ICS\INTERFACE\TCA9617B.PDF
U63 = TPS62097RWKT_VQFNHR11: IC 2A SYNCHRONOUS STEP DOWN CONVERTER WITH IDCS CONTROL VQFN-HR11; Chkd/date: MANIRAJA/270917; Crtd /date: MANIRAJA/270917; Custom_Duty: 15%; Customs_HS_Code: 85423100; Distributor_name: DIGIKEY; Distributor_part_number: 296-43330-1-ND; Height: 1.00MM; Mfr_name: TEXAS INSTRUMENTS; Mistral Part No: 142017090025-R; Package: VQFN-HR11; Part_type: ICS\POWER\CONVERTER; Project: TI_MAXIE_CPB; RoHS: RoHS; Temperature: -40°C+125°C; Tolerance: NA; Voltage: NA; Wattage: NA; Weight: NA; Datasheet: Y:\MIS_DATABASE\DATASHEETS\ICS\POWER\TPS62097.PDF
C148 C149 C154 C156-C158 C160 C162 C163 = CAP: CAP CERAMIC 1uF 16V 10% X5R 0402; Chkd/date: MANIRAJA/210817; Crtd /date: MANIRAJA/210817; Custom_Duty: 15%; Customs_HS_Code: 85322990; Distributor_name: DIGIKEY; Distributor_part_number: 587-3709-1-ND; Height: 0.55MM; Mfr_name: TAIYO YUDEN; Mfr_part_number: EMK105BJ105KVHF; Mistral Part No: 120011050002-R; Package: 0402; Part_type: CAPACITORS\CERAMIC; Project: TI_RF_DC CARD; RoHS: RoHS; Temperature: -55°C+85°C; Tolerance: 10%; Voltage: 16V; Wattage: NA; Weight: 0.65mg; Datasheet: Y:\MIS_DATABASE\DATASHEETS\CAPACITORS\EMK105BJ105KVHF.PDF
C159 = CAP: CAP CERAMIC 0.01uF 50V 10% X7R 0402; Alternate_mfr_name_A: MURATA; Alternate_mfr_part_number_A: GRM155R71H103KA88D; Chkd/date: SHREESHAIL/301105; Crtd /date: MAZHAR/040505; Custom_Duty: 15%; Customs_HS_Code: 85322990; Distributor_name: DIGIKEY; Distributor_name_A: DIGIKEY; Distributor_part_number: 399-3066-1-ND; Distributor_part_number_A: 490-4516-1-ND; Height: 0.55MM; Mfr_name: KEMET; Mfr_part_number: C0402C103K5RACTU; Mistral Part No: 120009030025-R; Package: 0402; Part_type: CAPACITORS\CERAMIC; Project: G4_SVGA; RoHS: RoHS; Tolerance: 10%; Voltage: 50V; Datasheet: Y:\MIS_DATABASE\DATASHEETS\CAPACITORS\KEMET-C08.PDF
FL5 = EMIFILTER_IND: FERRITE CHIP 120E 1.3A 0402; Chkd/date: VASANTHA/010117; Crtd /date: CHAITHANYA/150312; Custom_Duty: 24%; Customs_HS_Code: 85437099; Distributor_name: DIGIKEY; Distributor_part_number: 490-5203-1-ND; Footprint Path: Y:\MIS_DATABASE\Library\ALTIUM_TOOL\PCB_FOOTPRINTS\Altium_Footprint_Lib.PcbLib; Height: 0.55MM; Library Path: Y:\MIS_DATABASE\Library\ALTIUM_TOOL\SCHEMATICS_PARTS\MS_FILTER_Library.schlib; Mfr_name: MURATA; Mfr_part_number: BLM15PD121SN1; Mistral Part No: 130012030043-R; Package: 0402; Part_type: MISC\FILTER; Project: GEN_3-8; RoHS: RoHS; Temperature: -55°C+125°C; Tolerance: 25%; Voltage: NA; Wattage: NA; Weight: 0.65mg; Datasheet: Y:\MIS_DATABASE\DATASHEETS\DISCRETES\INDUCTORS\BLM18K-SERIES.PDF
J3 = CON_RJ45-28_LPJG17512AONL: CON JACK RJ45 28POS REGISTERED FEMALE RA TH; Chkd/date: MANIRAJA/010817; Crtd /date: MANIRAJA/010817; Custom_Duty: 24%; Customs_HS_Code: 85369090; Distributor_name: NA; Distributor_part_number: NA; Height: 25.30MM; Mfr_name: LINK-PP; Mfr_part_number: LPJG17512AONL; Mistral Part No: 150017080001-R; Package: THRU-HOLE; Part_type: CONNECTOR\JACK; Project: TI_SVB_DUT; RoHS: RoHS; TEXT2: ETH1; Temperature: 0°C+70°C; Tolerance: NA; Voltage: NA; Wattage: NA; Weight: NA; TEXT1: ETH0; Datasheet: Y:\MIS_DATABASE\DATASHEETS\CONNECTORS\LPJG17512AONL.PDF
Q16 Q20 Q22 = MOSFET_BSS138LT1G: IC MOSFET N-CHANNEL 50V, SOT23-3; Chkd/date: VASANTHA/150416; Crtd /date: JEBRAN/060416; Custom_Duty: 15%; Customs_HS_Code: 85423100; Distributor_name: MOUSER; Distributor_part_number: 863-BSS138LT1G; Height: 1.11MM; Mfr_name: ON SEMICONDUCTOR; Mistral Part No: 142016040001-R; Package: SOT23-3; Part_type: ICS\POWER\MOSFET; Project: LRDE_ABCM; RoHS: RoHS; Temperature: -55°C+150°C; Tolerance: NA; Voltage: 50V; Wattage: NA; Weight: NA; Datasheet: Y:\MIS_DATABASE\DATASHEETS\DISCRETES\TRANSISTORS_FETS\BSS138LT1G.PDF
R109 R125 = RESISTOR: RES 2.2K 1/16W 5% 0402; Chkd/date: VASANTHA/061216; Crtd /date: BAVISH/021210; Custom_Duty: 15%; Customs_HS_Code: 85332119; Distributor_name: DIGIKEY; Distributor_part_number: 311-2.2KJRCT-ND; Footprint Path: VALUE IS VAILABLE 3 TIMES; Height: 0.40MM; Mfr_name: YAGEO AMERICA; Mfr_part_number: RC0402JR-072K2L; Mistral Part No: 110010120018-R; Package: 0402; Part_type: RESISTORS\FIXED; Project: TE4; RoHS: RoHS; Temperature: -55°C+155°C; Tolerance: 5%; Voltage: NA; Wattage: 1/16W; Weight: 0.65mg; Datasheet: Y:\MIS_DATABASE\DATASHEETS\RESISTORS\YAGEO.PDF
R116 R118 R121 R123 R280-R282 R288 R292-R295 R298-R300 = RESISTOR: RES 2.49K 1/16W 1% 0402; Chkd/date: VASANTHA/270516; Crtd /date: VASANTHA/270516; Custom_Duty: 15%; Customs_HS_Code: 85332119; Distributor_name: DIGIKEY; Distributor_part_number: 311-2.49KLRCT-ND; Height: 0.40MM; Mfr_name: YAGEO AMERICA; Mfr_part_number: RC0402FR-072K49L; Mistral Part No: 110016050020-R; Package: 0402; Part_type: RESISTORS\FIXED; Project: TMDXCSKCC; RoHS: RoHS; Temperature: -55°C+155°C; Tolerance: 1%; Voltage: NA; Wattage: 1/16W; Weight: NA; Datasheet: Y:\MIS_DATABASE\DATASHEETS\RESISTORS\RC0402FR.PDF
R124 = RESISTOR: RES 11K 1/16W 1% 0402; Chkd/date: VASANTHA/251115; Crtd /date: VASANTHA/251115; Custom_Duty: 15%; Customs_HS_Code: 85332119; Distributor_name: DIGIKEY; Distributor_part_number: 311-11.0KLRCT-ND; Height: 0.40MM; Mfr_name: YAGEO AMERICA; Mfr_part_number: RC0402FR-0711KL; Mistral Part No: 110015110012-P; Package: 0402; Part_type: RESISTORS\FIXED; Project: TI_VLAN_SWITCH; RoHS: Pb-Free; Temperature: -55°C+155°C; Tolerance: 1%; Voltage: NA; Wattage: 1/16W; Weight: 0.65mg; Datasheet: Y:\MIS_DATABASE\DATASHEETS\RESISTORS\YAGEO-RC0402.PDF
R240 R245 R246 = RESISTOR: RES 220E 1/16W 5% 0402; Chkd/date: VASANTHA/291216; Crtd /date: GEETHA/260406; Custom_Duty: 15%; Customs_HS_Code: 85332119; Distributor_name: DIGIKEY; Distributor_part_number: P220JCT-ND; Footprint Path: Y:\MIS_DATABASE\Library\ALTIUM_TOOL\PCB_FOOTPRINTS\Altium_Footprint_Lib.PcbLib; Height: 0.40MM; Library Path: Y:\MIS_DATABASE\Library\ALTIUM_TOOL\SCHEMATICS_PARTS\MS_DISCRETE_Library.schlib; Mfr_name: PANASONIC-ECG; Mfr_part_number: ERJ-2GEJ221X; Mistral Part No: 110009030506-R; Package: 0402; Part_type: RESISTORS\FIXED; Project: RED EYE; RoHS: RoHS; Temperature: -55°C+155°C; Tolerance: 5%; Voltage: NA; Wattage: 1/16W; Weight: 0.8g/1000pcs; Datasheet: Y:\MIS_DATABASE\DATASHEETS\RESISTORS\ERJ12.PDF
R279 R287 R291 R297 = RESISTOR: RES 5.76K 1/10W 1% 0402; Chkd/date: MAZHAR/150709; Crtd /date: USMAN/220808; Custom_Duty: 15%; Customs_HS_Code: 85332119; Distributor_name: DIGIKEY; Distributor_part_number: P5.76KLCT-ND; Footprint Path: Y:\MIS_DATABASE\Library\ALTIUM_TOOL\PCB_FOOTPRINTS\Altium_Footprint_Lib.PcbLib; Height: 0.40MM; Library Path: Y:\MIS_DATABASE\Library\ALTIUM_TOOL\SCHEMATICS_PARTS\MS_DISCRETE_Library.schlib; Mfr_name: PANASONIC-ECG; Mfr_part_number: ERJ-2RKF5761X; Mistral Part No: 110009030945-R; Package: 0402; Part_type: RESISTORS\FIXED; Project: CPB; RoHS: RoHS; Tolerance: 1%; Wattage: 1/10W; Datasheet: Y:\MIS_DATABASE\DATASHEETS\RESISTORS\PAN-ERJSERIES.PDF
U8 = SN74LVC1G08DBVRE4_SOT23-5: IC SINGLE 2-INPUT POSITIVE AND GATE SOT23-5; Chkd/date: SUHAS/221010; Crtd /date: USMAN/151008; Custom_Duty: 15%; Customs_HS_Code: 85423100; Distributor_name: DIGIKEY; Distributor_part_number: SN74LVC1G08DBVRE4-ND; Height: 1.45MM; Mfr_name: TEXAS INSTRUMENTS; Mistral Part No: 141009060026-R; Part_type: ICS\DIGITAL\GATES; Project: KHAN_MAIN; RoHS: Sb/ Br FREE; Temperature: -40°C+85°C; Datasheet: Y:\MIS_DATABASE\DATASHEETS\ICS\DIGITAL\GATES\SN74LVC1G08.PDF
U52 = DP83867IRPAPT_HTQFP64: IC HIGH IMMUNITY 10/100/1000 Mb/s ETHERNET PHY LAYER TRANSCEIVER HTQFP64; Chkd/date: VASANTHA/250516; Crtd /date: VASANTHA/250516; Custom_Duty: 15%; Customs_HS_Code: 85423100; Distributor_name: DIGIKEY; Distributor_part_number: 296-41117-1-ND; Height: 1.20MM; Mfr_name: TEXAS INSTRUMENTS; Mistral Part No: 143016050002-R; Package: HTQFP64; Part_type: ICS\TELECOM\TRANSCEIVER; Project: TMDXCSKCC; RoHS: RoHS; Temperature: -40°C+85°C; Tolerance: NA; Voltage: NA; Wattage: NA; Weight: NA; Datasheet: Y:\MIS_DATABASE\DATASHEETS\ICS\DIGITAL\BUSTRANSCEIVER\DP83867I.PDF

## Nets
DGND: C12.2 C13.2 C38.2 C47.2 C48.2 C54.2 C55.2 C56.2 C57.2 C58.2 C60.2 C61.2 C104.2 C105.2 C111.2 C115.2 C116.2 C148.2 C149.2 C154.2 C155.2 C156.2 C157.2 C158.2 C159.2 C160.2 C161.2 C162.2 C163.2 C165.2 C173.2 C260.2 C267.2 J3.A10(GND) J16.13 J16.18 J16.19 J16.22 J16.25 J16.61 J16.62 J16.63 J16.64 J17.1 J17.2 J17.5 J17.6 J17.17 J17.21 J17.25 J17.29 J17.36 J17.40 J17.52 J17.56 J17.69 J17.73 J17.82 J17.85 J17.86 J17.89 J17.92 J17.96 J17.97 J17.101 J17.104 J17.105 J17.107 J17.108 J17.109 J17.111 J17.112 J17.113 J17.115 J17.116 J17.117 J17.118 J17.119 J17.120 J17.121 J17.122 J17.123 J17.124 J17.125 J17.126 J17.127 J17.128 Q16.2(S) Q20.2(S) Q22.2(S) R15.2 R118.2 R123.2 R124.1 R264.2 R265.2 R266.2 R267.2 R268.2 R280.2 R282.2 R288.2 R292.2 R294.2 R295.2 R298.2 R300.2 TP6.1(TP) U3.4(GND) U8.3(GND) U52.65(EP) U63.1(PGND) U63.11(AGND) ; also on sheet 6 7 8 9 11 12
VCC1V1_PG: R12.1 TP29.1(TP) U63.5(PG)
VCC_1V0: C116.1 J16.56 J16.58 J16.60
VCC_1V1: C47.1 C55.1 C56.1 C61.1 C149.1 C155.1 C156.1 C157.1 C159.1 C162.1 C267.1 L6.2 R435.1 TP28.1(TP) U52.8(VDD1P1) U52.29(VDD1P1) U52.42(VDD1P1) U52.58(VDD1P1) U63.3(VOS) ; also on sheet 6 7 8
VCC_1V8: C38.1 C48.1 C57.1 C60.1 C105.1 C148.1 C158.1 C163.1 C165.1 FL5.1 J16.55 J16.57 J16.59 R82.2 R109.2 R116.1 R121.1 R125.2 R126.2 R127.2 R128.2 R279.2 R281.1 R287.2 R291.2 R293.1 R296.1 R297.2 R299.1 R302.2 U8.5(VCC) U52.23(VDDIO) U52.41(VDDIO) U52.57(VDDIO) ; also on sheet 6 7 8 11 12
VCC_2V5: C54.1 C58.1 C115.1 C154.1 C160.1 C161.1 J16.52 J16.54 U52.4(VDDA2P5) U52.12(VDDA2P5) ; also on sheet 6 7 8
VCC_3V3: C12.1 C13.1 C104.1 C260.1 J16.1 J16.3 J16.5 R12.2 R17.1 R21.1 R24.1 R240.2 R245.2 R246.1 U3.1(VCCA) U3.8(VCCB) U63.6(EN) U63.7(PVIN) U63.8(AVIN) ; also on sheet 6 7 8 9 11 12
VCC_5V0: C111.1 J16.2 J16.4 J16.6 ; also on sheet 11 12
CAN0_RX: J16.32 ; also on sheet 12
CAN0_STB: R234.2 ; also on sheet 12
CAN0_TX: J16.30 ; also on sheet 12
CAN1_RX: J16.36 ; also on sheet 12
CAN1_STB: R243.2 ; also on sheet 12
CAN1_TX: J16.34 ; also on sheet 12
EEPROM_A0: J16.40 ; also on sheet 12
EEPROM_A1: J16.42 ; also on sheet 12
EEPROM_A2: J16.44 ; also on sheet 12
EEPROM_I2C_SCL: J16.15 ; also on sheet 12
EEPROM_I2C_SDA: J16.17 ; also on sheet 12
ETH0/1_INTn: J17.18 R109.1 U52.60(INT/PWDN) ; also on sheet 6
ETH0/1_MDC: J17.59 U52.20(MDC) ; also on sheet 6
ETH0/1_MDIO: J17.53 R125.1 U52.21(MDIO) ; also on sheet 6
ETH0/1_RESETn: U8.4(Y) U52.59(RESET_N) ; also on sheet 6
ETH0_CLK: J17.3 U52.19(X_I)
ETH0_CLK_OUT: TP21.1(TP) U52.22(CLK_OUT)
ETH0_D0M: J3.A2(TD1-_1) U52.3(TD_M_A)
ETH0_D0P: J3.A1(TD1+_1) U52.2(TD_P_A)
ETH0_D1M: J3.A4(TD2-_1) U52.6(TD_M_B)
ETH0_D1P: J3.A3(TD2+_1) U52.5(TD_P_B)
ETH0_D2M: J3.A6(TD3-_1) U52.11(TD_M_C)
ETH0_D2P: J3.A5(TD3+_1) U52.10(TD_P_C)
ETH0_D3M: J3.A8(TD4-_1) U52.14(TD_M_D)
ETH0_D3P: J3.A7(TD4+_1) U52.13(TD_P_D)
ETH0_LED1: J3.A11 Q22.3(D)
ETH0_LED2: J3.A13 Q20.3(D) R245.1
ETH0_LED3: J3.A14 Q16.3(D) R240.1
ETH0_LED_1000: R236.2 R445.2 U52.62(LED_1)
ETH0_LED_ACT: R254.1 U52.61(LED_2)
ETH0_LED_LINK: R299.2 R300.1 R436.2 R437.2 U52.63(LED_0)
ETH0_MII_COL: R247.2 U52.55(COL/GPIO)
ETH0_MII_CRS: R295.1 R296.2 U52.56(CS/GPIO)
ETH0_MII_RXER: J17.37 U52.54(RX_ER/GPIO)
ETH0_MII_TXC_R: R453.2 U52.30(TX_CLK)
ETH0_RGMII_RD0: J17.35 R121.2 R123.1 U52.44(RX_D0)
ETH0_RGMII_RD1: J17.39 U52.45(RX_D1)
ETH0_RGMII_RD2: J17.33 R116.2 R118.1 U52.46(RX_D2)
ETH0_RGMII_RD3: J17.23 U52.47(RX_D3)
ETH0_RGMII_RD4: R444.2 U52.48(RX_D4/GPIO)
ETH0_RGMII_RD5: R281.2 R282.1 U52.49(RX_D5/GPIO)
ETH0_RGMII_RD6: R290.2 U52.50(RX_D6/GPIO)
ETH0_RGMII_RD7: R293.2 R294.1 U52.51(RX_D7/GPIO)
ETH0_RGMII_RX_CTL: J17.31 R291.1 R292.1 U52.53(RX_DV/RX_CTRL)
ETH0_RGMII_RXC: J17.27 U52.43(RX_CLK)
ETH0_RGMII_TD0: J17.15 R269.1 R271.1
ETH0_RGMII_TD0_R: R269.2 R278.2 U52.38(TX_D0)
ETH0_RGMII_TD1: J17.9 R270.1 R272.1
ETH0_RGMII_TD1_R: R270.2 R271.2 U52.37(TX_D1)
ETH0_RGMII_TD2: J17.11 R273.1 R274.1
ETH0_RGMII_TD2_R: R272.2 R273.2 U52.36(TX_D2)
ETH0_RGMII_TD3: J17.7 R275.1 R276.1
ETH0_RGMII_TD3_R: R274.2 R275.2 U52.35(TX_D3)
ETH0_RGMII_TD4_R: R264.1 U52.34(TX_D4)
ETH0_RGMII_TD5_R: R265.1 U52.33(TX_D5)
ETH0_RGMII_TD6_R: R266.1 U52.32(TX_D6)
ETH0_RGMII_TD7_R: R267.1 U52.31(TX_D7)
ETH0_RGMII_TX_CTL: J17.13 R277.1 R278.1
ETH0_RGMII_TX_CTL_R: R276.2 R277.2 U52.52(TX_EN/TX_CTRL)
ETH0_RGMII_TXC: J17.19 R452.1 R453.1
ETH0_RGMII_TXC_R: R452.2 U52.40(GTX_CLK)
ETH1_CLK: J17.4 ; also on sheet 6
ETH1_LED_LINK: R438.2 R441.1 ; also on sheet 6
ETH1_MII_RXER: J17.8 ; also on sheet 6
ETH1_RGMII_RD0: J17.30 ; also on sheet 6
ETH1_RGMII_RD1: J17.34 ; also on sheet 6
ETH1_RGMII_RD2: J17.32 ; also on sheet 6
ETH1_RGMII_RD3: J17.28 ; also on sheet 6
ETH1_RGMII_RX_CTL: J17.26 ; also on sheet 6
ETH1_RGMII_RXC: J17.54 ; also on sheet 6
ETH1_RGMII_TD0: J17.50 ; also on sheet 6
ETH1_RGMII_TD1: J17.46 ; also on sheet 6
ETH1_RGMII_TD2: J17.44 ; also on sheet 6
ETH1_RGMII_TD3: J17.42 ; also on sheet 6
ETH1_RGMII_TX_CTL: J17.48 ; also on sheet 6
ETH1_RGMII_TXC: J17.38 ; also on sheet 6
ETH2/3_INTn: J17.49 ; also on sheet 7 8
ETH2/3_MDC: J17.95 ; also on sheet 7 8
ETH2/3_MDIO: J17.99 ; also on sheet 7 8
ETH2_CLK: J17.106 ; also on sheet 7
ETH2_LED_LINK: R439.2 R440.2 ; also on sheet 7
ETH2_MII_RXER: J17.60 ; also on sheet 7
ETH2_RGMII_RD0: J17.88 ; also on sheet 7
ETH2_RGMII_RD1: J17.76 ; also on sheet 7
ETH2_RGMII_RD2: J17.80 ; also on sheet 7
ETH2_RGMII_RD3: J17.90 ; also on sheet 7
ETH2_RGMII_RX_CTL: J17.78 ; also on sheet 7
ETH2_RGMII_RXC: J17.84 ; also on sheet 7
ETH2_RGMII_TD0: J17.110 ; also on sheet 7
ETH2_RGMII_TD1: J17.114 ; also on sheet 7
ETH2_RGMII_TD2: J17.100 ; also on sheet 7
ETH2_RGMII_TD3: J17.102 ; also on sheet 7
ETH2_RGMII_TX_CTL: J17.98 ; also on sheet 7
ETH2_RGMII_TXC: J17.94 ; also on sheet 7
ETH3_CLK: J17.103 ; also on sheet 8
ETH3_LED_LINK: R442.1 R443.1 ; also on sheet 8
ETH3_MII_RXER: J17.55 ; also on sheet 8
ETH3_RGMII_RD0: J17.63 ; also on sheet 8
ETH3_RGMII_RD1: J17.67 ; also on sheet 8
ETH3_RGMII_RD2: J17.77 ; also on sheet 8
ETH3_RGMII_RD3: J17.75 ; also on sheet 8
ETH3_RGMII_RX_CTL: J17.65 ; also on sheet 8
ETH3_RGMII_RXC: J17.71 ; also on sheet 8
ETH3_RGMII_TD0: J17.79 ; also on sheet 8
ETH3_RGMII_TD1: J17.91 ; also on sheet 8
ETH3_RGMII_TD2: J17.93 ; also on sheet 8
ETH3_RGMII_TD3: J17.83 ; also on sheet 8
ETH3_RGMII_TX_CTL: J17.81 ; also on sheet 8
ETH3_RGMII_TXC: J17.87 ; also on sheet 8
ETH_LED1: J17.10 TP30.1(TP) ; also on sheet 9
ETH_LED2: J17.24 TP31.1(TP) ; also on sheet 9
ETH_LED3: J17.12 TP32.1(TP) ; also on sheet 9
ETH_LED4: J17.47 TP33.1(TP) ; also on sheet 9
ETH_LED5: J17.70 TP34.1(TP) ; also on sheet 9
ETH_LED6: J16.31 TP35.1(TP) ; also on sheet 9
ETH_LED7: J17.68 TP36.1(TP) ; also on sheet 9
ETH_LED8: J16.29 TP37.1(TP) ; also on sheet 9
GPIO_ETH0/1_RESETn: J17.45 R82.1 U8.1(A)
GPIO_ETH2/3_RESETn: J17.43 ; also on sheet 7
IDK_I2C_SCL: R24.2 U3.7(SCLB) ; also on sheet 11
IDK_I2C_SCL_C: J16.21 U3.2(SCLA)
IDK_I2C_SDA: R21.2 U3.6(SDAB) ; also on sheet 11
IDK_I2C_SDA_C: J16.23 U3.3(SDAA)
IDK_IOEXP_LDn_1V8: J17.62 ; also on sheet 11
IDK_SPI_CLK_3V3: J16.20 ; also on sheet 11
IDK_SPI_CSn_3V3: J16.24 ; also on sheet 11
IDK_SPI_MISO_3V3: J16.28 ; also on sheet 11
PORz_OUT: J16.38 U8.2(B) ; also on sheet 7
PRG0_IEP0_LATCH_IN0: J17.14 R234.1 TP15.1(TP)
PRG0_IEP1_LATCH_IN0: J17.51 R243.1 TP10.1(TP)
PRG1_IEP0_LATCH_IN0: J17.72 TP2.1(TP)
PRG1_IEP1_LATCH_IN0: J16.27 TP7.1(TP)
RS485_UART_RTSn: J17.74 ; also on sheet 12
RS485_UART_RX: J17.64 ; also on sheet 12
RS485_UART_TX: J17.61 ; also on sheet 12
N5126218: J3.A12 R246.2
N5249997: R297.1 R298.1 R445.1
N16747981: Q22.1(G) R254.2
N16748023: Q20.1(G) R247.1
N16748137: Q16.1(G) R236.1
N16865556: FL5.2 J3.A9(VCC)
N16893791: R17.2 U3.5(EN)
N17583874: J17.66 R440.1
N17583882: J17.16 R436.1
N17622810: R126.1 U52.25(JTAG_CLK)
N17622814: R128.1 U52.27(JTAG_TMS)
N17622987: R127.1 U52.28(JTAG_TDI)
N17624319: TP20.1(TP) U52.17(VDDA1P8) U52.64(VDDA1P8)
N17624985: R124.2 U52.15(RBIAS)
N17641854: R268.1 U52.39(TX_ER)
N17642927: R279.1 R280.1 R444.1
N17646237: R287.1 R288.1 R290.1
N17654482: R302.1 U52.24(JTAG_TRSTN)
N17705365: C173.1 U63.9(SS/TR)
N17705401: R15.1 R435.2 U63.4(FB)
N17705455: L6.1 U63.2(SW)
N17744835: J17.20 R437.1
N17745499: J17.22 R438.1
N17745526: J17.58 R439.1
N17745682: J17.41 R441.2
N17745712: J17.57 R442.2
N17745754: J16.33 R443.2

Not connected (* = marked no-connect by the designer): J3 SH1* SH2*; J16 7* 8* 9* 10* 11* 12* 14* 16* 26* 35* 37* 39* 41* 43* 45* 46* 47* 48* 49* 50* 51* 53*; U52 1(RESERVED4)* 7(RESERVED3)* 9(RESERVED2)* 16(RESERVED1)* 18(X_O)* 26(JTAG_TDO)*; U63 10(MODE)*

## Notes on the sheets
sheet 1
- MAXWELL INDUSTRIAL APPLICATION BOARD
- TABLE OF CONTENTS
- PAGE
- CONTENTS
- REV
- E4
- 01
- TABLE OF CONTENTS
- VER
- 1.0
- 02
- REVISION HISTORY
- 03
- BLOCK DIAGRAM
- 04
- STACKUP CONNECTOR
- 05
- CAN/RS485/BOARD ID INTERFACE
- 06
- RGMII ETHERNET PHY 0
- 07
- RGMII ETHERNET PHY 1
- 08
- RGMII ETHERNET PHY 2
- 09
- RGMII ETHERNET PHY 3
- 10
- LED
- 11
- SPI/I2C IO EXPANDER
- 12
- HARDWARE SCHEMATICS
sheet 2
- REVISION HISTORY
- VER #
- DATE
- DESCRIPTION OF CHANGES
- AUTHOR
- REVIEWED  BY
- APPROVED  BY
- 0.1
- 17th AUG 2018
- Drafted from Rev E3, Ver 1.0 schematics.
- Mistral Design Team
- AJIT MB
- AJIT MB
- 0.2
- 17th AUG 2018
- Added TX_CLK jumper options to connect MII& RGMII mode  and
   added Pullup on  IDK_SPI_CSn_3V3 net
- Mistral Design Team
- AJIT MB
- AJIT MB
- Added Test Points on EDC_SYNC_OUT signals
- Mistral Design Team
- AJIT MB
- AJIT MB
- 0.3
- 23rd AUG 2018
- Baselined
- Mistral Design Team
- AJIT MB
- AJIT MB
- 1.0
- 23rd AUG 2018
sheet 3
- BLOCK DIAGRAM
sheet 5
- STRAPPING RESISTORS
- RGMII Mode:
  Mount : R269, R270, R273, R275, R277,R452
  Unmount : R271, R272, R274, R276, R278, R290, R444, R445 ,R453
- Auto_neg =Enabled
  ANEGsel 10/100/1000
- PHY ADD = 00000
- MII Mode:
  Mount : R271, R272, R274, R276, R278, R290, R444, R445,R453
  Unmount : R269, R270, R273, R275, R277,R452
